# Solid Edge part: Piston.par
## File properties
Title: Piston
Author: Dan
Template: Normal.par
Last saved by: Dan
Revision: 29
Application: Solid Edge
Density: 0 kg/mm^3
Accuracy: 0.99
Document Number: P52-012
Project Name: Piston Pump P52
Material: steel en19
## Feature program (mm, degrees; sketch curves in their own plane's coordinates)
sketch for "unnamed Protrusion 1" plane through (0, 0, 0) normal (1, 0, 0) x-axis (0, 1, 0)
  circle centre (0, 0) radius 10
extrude "unnamed Protrusion 1" add finite 62.7 along -normal
sketch for "unnamed RevolvedCutout 1" plane through (0, 0, 0) normal (0, -1, 0) x-axis (1, 0, 0)
  line (-12.7, 10) -> (-12.7, 9.95)
  line (-12.7, 9.95) -> (-2.0475, 9.95)
  line (-2.0475, 9.95) -> (0, 3.253)
revolve "unnamed RevolvedCutout 1" cut finite 360 deg about sketch line (-1.4739, 0) -> (-13.5916, 0)
sketch for "Hole_1" plane through (-62.7, 0, 0) normal (-1, 0, 0) x-axis (0, 0, 1)
  hole centre (0, 0) bore radius 4
hole "Hole_1" diameter 8 finite  CounterBoreDepth = 45 mm; CounterSinkAngle = 118 deg; VBottomAngle = 118 deg
sketch for "Hole_2" plane through (2.7621, 7.7072, 0) normal (0.422618, 0.906308, 0) x-axis (0, 0, 1)
  hole centre (0, -9.8068) bore radius 3
hole "Hole_2" diameter 6 through
pattern "unnamed Pattern 1" of "Hole_2"
hole "unnamed Hole 1" through
hole "unnamed Hole 2" through
hole "unnamed Hole 3" through
chamfer "Chamfer_1" setback 1
chamfer "Chamfer_2" setback 0.5
sketch for "unnamed RevolvedCutout 2" plane through (0, 0, 0) normal (0, 0, 1) x-axis (1, 0, 0)
  line (-11.7101, 4.55) -> (-11.7101, 1.8204)
  line (-14.127, 4.55) -> (-11.7101, 4.55)
  line (-15.0268, 4.8604) -> (-14.127, 4.55)
  line (-16.7, 7.25) -> (-15.0268, 4.8604)
  line (-16.7, 8) -> (-16.7, 7.25)
  line (-61.7, 8) -> (-16.7, 8)
  line (-62.7, 9) -> (-61.7, 8)
  dimension (linear) = 61.7
revolve "unnamed RevolvedCutout 2" cut full turn 360 deg about sketch line (-12.8, 0) -> (-17.8, 0)
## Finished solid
Body 1: solid body, 27 faces, 53 edges, 24 vertices.
  Faces by surface: cylinder 13, plane 8, cone 6
  Edges by curve: circle 21, intersection 20, ellipse 12
Bounding box of the edges (mm): 62.700 x 20.000 x 20.000, from (-62.7, -10, -10) to (0, 10, 10).
Cylindrical faces by radius (mm): R3 x4, R4 x5, R4.55 x1, R8 x1, R9.95 x1, R10 x1
Conical faces (half-angle, radius in mm at the cone's reference point): 19.0326 deg R4.55 x1, 45 deg R9 x1, 45 deg R9.5 x1, 55 deg R4.8604 x1, 59 deg R4 x1, 73 deg R9.95 x1
Planar faces by outward normal: +x 2, -x 6
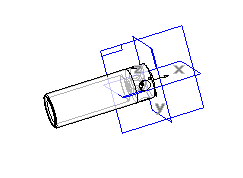
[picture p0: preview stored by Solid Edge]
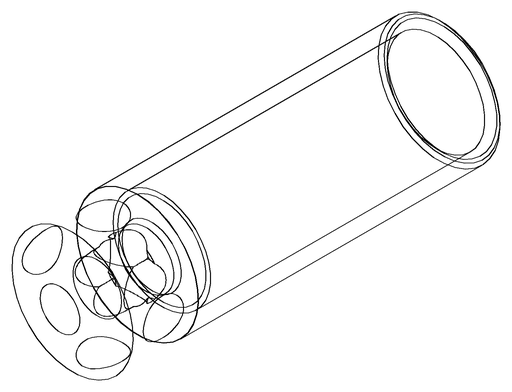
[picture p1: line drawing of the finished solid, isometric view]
